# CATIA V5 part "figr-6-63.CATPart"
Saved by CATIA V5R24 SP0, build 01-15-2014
Part number: Part1
Bounding box of the stored display mesh (mm): x -50.648 to 50.648, y -72.183 to 72.183, z -40 to 40
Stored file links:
  D:\KAVITA\CATIA V5-6R2014 Project_ Kavita\CATIA V5-6R2014_partfiles\Partfiles\c06_catia_v5-6r2014_prt\figr-6-63.CATPart
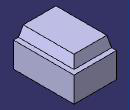
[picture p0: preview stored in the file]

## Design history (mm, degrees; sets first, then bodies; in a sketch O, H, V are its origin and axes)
Set1
  Plane1: type Offset, RefPlane xy-plane, Offset 20
Body1 (main body)
  Sketch1 on xy-plane, origin (0, 0, 0), H (1, 0, 0), V (0, 1, 0)
    line L1 (-50.6478, 72.1832) -> (50.6478, 72.1832)
    line L2 (50.6478, 72.1832) -> (50.6478, -72.1832)
    line L3 (50.6478, -72.1832) -> (-50.6478, -72.1832)
    line L4 (-50.6478, -72.1832) -> (-50.6478, 72.1832)
    axis line L5 (50.6478, -72.1832) -> (-50.6478, 72.1832)
    horizontal: L1 H, L3 H
    vertical: L2 V, L4 V
    midpoint: O L5
  Pad1: profile Sketch1, direction (0, 0, 1), length 40, mirrored extent
  Draft1: Angle 30, Neutral xy-plane, Parting Plane1, PullDir (0, 0, 1), SupportToDraft (face of Pad1; face of Pad1)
